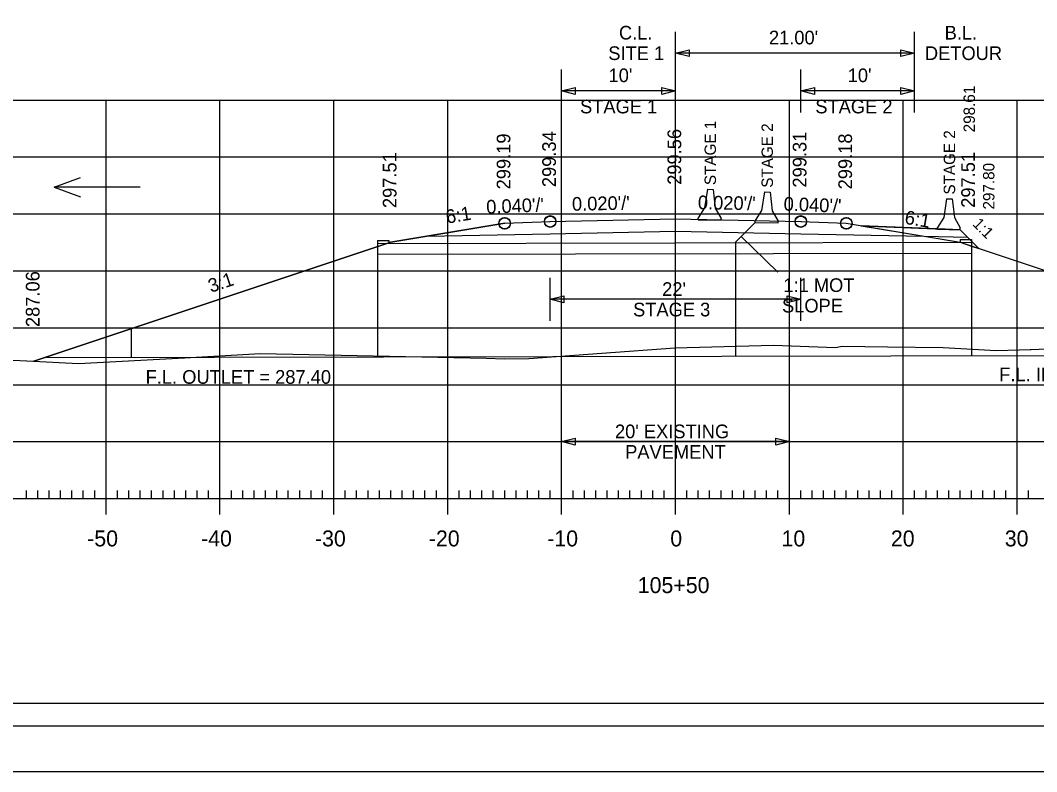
# Model space of a CAD drawing. Extents: x 1368713 to 1370673, y 380279 to 380950.
# Drawn here: x 1370094.8 to 1370184, y 380523.8 to 380589.8 of the extents above; entities that cross this region are included whole.
import ezdxf

# ---------------------------------------------------------------- set-up
doc = ezdxf.new("R2010")
doc.units = 0
for name, color, linetype in [('R_Alt Surface', 7, 'Continuous'), ('R_Axis', 7, 'Continuous'), ('R_Axis Annot', 7, 'Continuous'), ('R_Border', 7, 'Continuous'), ('R_CONC BARRIER', 7, 'Continuous'), ('R_Detour', 7, 'Continuous'), ('R_Exist Surface', 7, 'Continuous'), ('R_Fin Surface', 7, 'Continuous'), ('R_Grid', 7, 'Continuous'), ('R_No Plot', 7, 'Continuous'), ('R_ROW Annot', 7, 'Continuous'), ('R_Stage 3 EW', 7, 'Continuous'), ('R_Water', 7, 'Continuous'), ('R_Water Annot', 7, 'Continuous'), ('R_Xsect Elev', 7, 'Continuous'), ('R_Xsect Slope', 7, 'Continuous')]:
    doc.layers.add(name, color=color, linetype=linetype)

msp = doc.modelspace()

# ---------------------------------------------------------------- linework, layer by layer
for points in [[(1370141.283, 380572.113), (1370141.283, 380572.102), (1370141.283, 380572.091), (1370141.283, 380572.079), (1370141.283, 380572.068)], [(1370163.283, 380572.102), (1370163.283, 380572.091), (1370163.283, 380572.079), (1370163.283, 380572.068)]]:
    msp.add_lwpolyline(points)
at = {"layer": 'R_Alt Surface'}
for points in [[(1370137.283, 380571.931), (1370127.283, 380570.264)], [(1370167.283, 380571.931), (1370177.283, 380570.264)], [(1370130.442, 380570.791), (1370141.283, 380571.007), (1370152.283, 380571.227), (1370163.283, 380571.007), (1370174.123, 380570.791)], [(1370177.283, 380571.364), (1370178.139, 380570.508)], [(1370127.283, 380570.264), (1370095.937, 380559.815)], [(1370174.123, 380570.791), (1370177.932, 380570.714)], [(1370177.283, 380570.264), (1370207.014, 380560.354)]]:
    msp.add_lwpolyline(points, dxfattribs=at)
at = {"layer": 'R_Axis'}
for p, q in [((1370102.283, 380546.354), (1370102.283, 380549.154)), ((1370112.283, 380546.354), (1370112.283, 380549.154)), ((1370122.283, 380546.354), (1370122.283, 380549.154)), ((1370132.283, 380546.354), (1370132.283, 380549.154)), ((1370142.283, 380546.354), (1370142.283, 380549.154)), ((1370152.283, 380546.354), (1370152.283, 380549.154)), ((1370162.283, 380546.354), (1370162.283, 380549.154)), ((1370172.283, 380546.354), (1370172.283, 380549.154)), ((1370182.283, 380546.354), (1370182.283, 380549.154)), ((1370095.283, 380547.754), (1370095.283, 380548.454)), ((1370096.283, 380547.754), (1370096.283, 380548.454)), ((1370097.283, 380547.754), (1370097.283, 380548.454)), ((1370098.283, 380547.754), (1370098.283, 380548.454)), ((1370099.283, 380547.754), (1370099.283, 380548.454)), ((1370100.283, 380547.754), (1370100.283, 380548.454)), ((1370101.283, 380547.754), (1370101.283, 380548.454)), ((1370103.283, 380547.754), (1370103.283, 380548.454)), ((1370104.283, 380547.754), (1370104.283, 380548.454)), ((1370105.283, 380547.754), (1370105.283, 380548.454)), ((1370106.283, 380547.754), (1370106.283, 380548.454)), ((1370107.283, 380547.754), (1370107.283, 380548.454)), ((1370108.283, 380547.754), (1370108.283, 380548.454)), ((1370109.283, 380547.754), (1370109.283, 380548.454)), ((1370110.283, 380547.754), (1370110.283, 380548.454)), ((1370111.283, 380547.754), (1370111.283, 380548.454)), ((1370113.283, 380547.754), (1370113.283, 380548.454)), ((1370114.283, 380547.754), (1370114.283, 380548.454)), ((1370115.283, 380547.754), (1370115.283, 380548.454)), ((1370116.283, 380547.754), (1370116.283, 380548.454)), ((1370117.283, 380547.754), (1370117.283, 380548.454)), ((1370118.283, 380547.754), (1370118.283, 380548.454)), ((1370119.283, 380547.754), (1370119.283, 380548.454)), ((1370120.283, 380547.754), (1370120.283, 380548.454)), ((1370121.283, 380547.754), (1370121.283, 380548.454)), ((1370123.283, 380547.754), (1370123.283, 380548.454)), ((1370124.283, 380547.754), (1370124.283, 380548.454)), ((1370125.283, 380547.754), (1370125.283, 380548.454)), ((1370126.283, 380547.754), (1370126.283, 380548.454)), ((1370127.283, 380547.754), (1370127.283, 380548.454)), ((1370128.283, 380547.754), (1370128.283, 380548.454)), ((1370129.283, 380547.754), (1370129.283, 380548.454)), ((1370130.283, 380547.754), (1370130.283, 380548.454)), ((1370131.283, 380547.754), (1370131.283, 380548.454)), ((1370133.283, 380547.754), (1370133.283, 380548.454)), ((1370134.283, 380547.754), (1370134.283, 380548.454)), ((1370135.283, 380547.754), (1370135.283, 380548.454)), ((1370136.283, 380547.754), (1370136.283, 380548.454)), ((1370137.283, 380547.754), (1370137.283, 380548.454)), ((1370138.283, 380547.754), (1370138.283, 380548.454)), ((1370139.283, 380547.754), (1370139.283, 380548.454)), ((1370140.283, 380547.754), (1370140.283, 380548.454)), ((1370141.283, 380547.754), (1370141.283, 380548.454)), ((1370143.283, 380547.754), (1370143.283, 380548.454)), ((1370144.283, 380547.754), (1370144.283, 380548.454)), ((1370145.283, 380547.754), (1370145.283, 380548.454)), ((1370146.283, 380547.754), (1370146.283, 380548.454)), ((1370147.283, 380547.754), (1370147.283, 380548.454)), ((1370148.283, 380547.754), (1370148.283, 380548.454)), ((1370149.283, 380547.754), (1370149.283, 380548.454)), ((1370150.283, 380547.754), (1370150.283, 380548.454)), ((1370151.283, 380547.754), (1370151.283, 380548.454)), ((1370153.283, 380547.754), (1370153.283, 380548.454)), ((1370154.283, 380547.754), (1370154.283, 380548.454)), ((1370155.283, 380547.754), (1370155.283, 380548.454)), ((1370156.283, 380547.754), (1370156.283, 380548.454)), ((1370157.283, 380547.754), (1370157.283, 380548.454)), ((1370158.283, 380547.754), (1370158.283, 380548.454)), ((1370159.283, 380547.754), (1370159.283, 380548.454)), ((1370160.283, 380547.754), (1370160.283, 380548.454)), ((1370161.283, 380547.754), (1370161.283, 380548.454)), ((1370163.283, 380547.754), (1370163.283, 380548.454)), ((1370164.283, 380547.754), (1370164.283, 380548.454)), ((1370165.283, 380547.754), (1370165.283, 380548.454)), ((1370166.283, 380547.754), (1370166.283, 380548.454)), ((1370167.283, 380547.754), (1370167.283, 380548.454)), ((1370168.283, 380547.754), (1370168.283, 380548.454)), ((1370169.283, 380547.754), (1370169.283, 380548.454)), ((1370170.283, 380547.754), (1370170.283, 380548.454)), ((1370171.283, 380547.754), (1370171.283, 380548.454)), ((1370173.283, 380547.754), (1370173.283, 380548.454)), ((1370174.283, 380547.754), (1370174.283, 380548.454)), ((1370175.283, 380547.754), (1370175.283, 380548.454)), ((1370176.283, 380547.754), (1370176.283, 380548.454)), ((1370177.283, 380547.754), (1370177.283, 380548.454)), ((1370178.283, 380547.754), (1370178.283, 380548.454)), ((1370179.283, 380547.754), (1370179.283, 380548.454)), ((1370180.283, 380547.754), (1370180.283, 380548.454)), ((1370181.283, 380547.754), (1370181.283, 380548.454)), ((1370183.283, 380547.754), (1370183.283, 380548.454)), ((1370012.283, 380547.754), (1370292.283, 380547.754))]:
    msp.add_line(p, q, dxfattribs=at)
at = {"layer": 'R_Border'}
msp.add_line((1370310.463, 380527.754), (1369994.283, 380527.754), dxfattribs=at)
at = {"layer": 'R_CONC BARRIER'}
for p, q in [((1370155.086, 380574.917), (1370155.586, 380574.907)), ((1370160.089, 380574.688), (1370160.589, 380574.678)), ((1370176.087, 380574.088), (1370176.587, 380574.078)), ((1370154.283, 380572.233), (1370154.286, 380572.399)), ((1370154.283, 380572.233), (1370156.282, 380572.193)), ((1370156.282, 380572.193), (1370156.286, 380572.359)), ((1370159.285, 380572.004), (1370159.288, 380572.171)), ((1370159.285, 380572.004), (1370161.284, 380571.964)), ((1370161.284, 380571.964), (1370161.288, 380572.131)), ((1370175.283, 380571.404), (1370175.286, 380571.571)), ((1370175.283, 380571.404), (1370177.283, 380571.364)), ((1370177.283, 380571.364), (1370177.286, 380571.531))]:
    msp.add_line(p, q, dxfattribs=at)
for points in [[(1370155.086, 380574.917), (1370154.835, 380573.279), (1370154.286, 380572.399)], [(1370155.586, 380574.907), (1370155.772, 380573.26), (1370156.286, 380572.359)], [(1370160.089, 380574.688), (1370159.837, 380573.05), (1370159.288, 380572.171)], [(1370160.589, 380574.678), (1370160.774, 380573.032), (1370161.288, 380572.131)], [(1370176.087, 380574.088), (1370175.835, 380572.45), (1370175.286, 380571.571)], [(1370176.587, 380574.078), (1370176.773, 380572.432), (1370177.286, 380571.531)]]:
    msp.add_lwpolyline(points, dxfattribs=at)
at = {"layer": 'R_Detour'}
for p, q in [((1370159.285, 380572.004), (1370157.545, 380570.264)), ((1370157.545, 380570.264), (1370157.545, 380560.264)), ((1370161.274, 380567.633), (1370158.057, 380570.776))]:
    msp.add_line(p, q, dxfattribs=at)
at = {"layer": 'R_Exist Surface'}
msp.add_lwpolyline([(1370092.874, 380559.963), (1370095.324, 380559.844), (1370099.854, 380559.631), (1370109.161, 380560.101), (1370115.838, 380560.503), (1370135.654, 380560.071), (1370137.277, 380560.019), (1370139.399, 380560.046), (1370152.219, 380560.988), (1370160.894, 380561.239), (1370166.34, 380561.02), (1370166.917, 380561.13), (1370170.893, 380561.071), (1370175.781, 380561.031), (1370180.44, 380560.773), (1370182.469, 380560.82), (1370183.433, 380560.838), (1370183.506, 380560.845), (1370201.143, 380561.59)], dxfattribs=at)
at = {"layer": 'R_Fin Surface'}
for points in [[(1370095.937, 380559.815), (1370127.283, 380570.264), (1370130.442, 380570.791), (1370137.283, 380571.931), (1370141.283, 380572.091), (1370152.283, 380572.311), (1370163.283, 380572.091), (1370167.283, 380571.931), (1370174.123, 380570.791), (1370177.283, 380570.264), (1370207.014, 380560.354), (1370220.94, 380564.996)], [(1370137.283, 380571.931), (1370141.283, 380572.091), (1370152.283, 380572.311), (1370163.283, 380572.091), (1370167.283, 380571.931)], [(1370168.599, 380571.711), (1370177.283, 380571.364)]]:
    msp.add_lwpolyline(points, dxfattribs=at)
at = {"layer": 'R_Grid'}
for p, q in [((1370012.283, 380582.754), (1370292.283, 380582.754)), ((1370102.283, 380547.754), (1370102.283, 380582.754)), ((1370112.283, 380547.754), (1370112.283, 380582.754)), ((1370122.283, 380547.754), (1370122.283, 380582.754)), ((1370132.283, 380547.754), (1370132.283, 380582.754)), ((1370142.283, 380547.754), (1370142.283, 380582.754)), ((1370152.283, 380547.754), (1370152.283, 380582.754)), ((1370162.283, 380547.754), (1370162.283, 380582.754)), ((1370172.283, 380547.754), (1370172.283, 380582.754)), ((1370182.283, 380547.754), (1370182.283, 380582.754)), ((1370012.283, 380577.754), (1370292.283, 380577.754)), ((1370012.283, 380572.754), (1370292.283, 380572.754)), ((1370012.283, 380567.754), (1370292.283, 380567.754)), ((1370012.283, 380562.754), (1370292.283, 380562.754)), ((1370012.283, 380557.754), (1370292.283, 380557.754)), ((1370012.283, 380552.754), (1370292.283, 380552.754)), ((1370012.283, 380547.754), (1370292.283, 380547.754))]:
    msp.add_line(p, q, dxfattribs=at)
at = {"layer": 'R_No Plot'}
for points in [[(1369981.875, 380737.108), (1370315.215, 380737.108), (1370315.215, 380523.771), (1369981.875, 380523.771)], [(1369996.283, 380731.214), (1370245.823, 380731.214), (1370245.823, 380721.334), (1370263.363, 380721.334), (1370287.463, 380721.334), (1370287.463, 380699.001), (1370308.463, 380699.001), (1370308.463, 380529.754), (1369996.283, 380529.754)], [(1369996.283, 380628.484), (1370308.463, 380628.484), (1370308.463, 380529.754), (1369996.283, 380529.754)]]:
    msp.add_lwpolyline(points, close=True, dxfattribs=at)
for centre in [(1370137.283, 380571.942), (1370137.283, 380571.931), (1370137.283, 380571.931), (1370137.283, 380571.919), (1370137.283, 380571.908), (1370141.283, 380572.102), (1370141.283, 380572.091), (1370141.283, 380572.091), (1370141.283, 380572.079), (1370141.283, 380572.068), (1370163.283, 380572.102), (1370163.283, 380572.091), (1370163.283, 380572.091), (1370163.283, 380572.079), (1370163.283, 380572.068), (1370167.283, 380571.942), (1370167.283, 380571.931), (1370167.283, 380571.931), (1370167.283, 380571.919), (1370167.283, 380571.908)]:
    msp.add_circle(centre, 0.5, dxfattribs=at)
at = {"layer": 'R_ROW Annot'}
for p, q in [((1370152.283, 380584.988), (1370152.283, 380588.756)), ((1370173.283, 380584.988), (1370173.283, 380588.756)), ((1370173.283, 380586.872), (1370152.283, 380586.872)), ((1370142.283, 380581.67), (1370142.283, 380585.439)), ((1370152.283, 380581.67), (1370152.283, 380585.439)), ((1370163.283, 380581.67), (1370163.283, 380585.439)), ((1370173.283, 380581.67), (1370173.283, 380585.439)), ((1370152.283, 380583.555), (1370142.283, 380583.555)), ((1370173.283, 380583.555), (1370163.283, 380583.555)), ((1370141.283, 380563.369), (1370141.283, 380567.138)), ((1370163.283, 380563.369), (1370163.283, 380567.138)), ((1370163.283, 380565.254), (1370141.283, 380565.254)), ((1370142.283, 380550.869), (1370142.283, 380554.638)), ((1370162.283, 380550.869), (1370162.283, 380554.638)), ((1370162.283, 380552.754), (1370142.283, 380552.754))]:
    msp.add_line(p, q, dxfattribs=at)
for points in [[(1370153.483, 380586.572), (1370152.283, 380586.872), (1370153.483, 380587.172)], [(1370172.083, 380587.172), (1370173.283, 380586.872), (1370172.083, 380586.572)], [(1370143.483, 380583.255), (1370142.283, 380583.555), (1370143.483, 380583.855)], [(1370151.083, 380583.855), (1370152.283, 380583.555), (1370151.083, 380583.255)], [(1370164.483, 380583.255), (1370163.283, 380583.555), (1370164.483, 380583.855)], [(1370172.083, 380583.855), (1370173.283, 380583.555), (1370172.083, 380583.255)], [(1370142.483, 380564.954), (1370141.283, 380565.254), (1370142.483, 380565.554)], [(1370162.083, 380565.554), (1370163.283, 380565.254), (1370162.083, 380564.954)], [(1370143.483, 380552.454), (1370142.283, 380552.754), (1370143.483, 380553.054)], [(1370161.083, 380553.054), (1370162.283, 380552.754), (1370161.083, 380552.454)]]:
    msp.add_lwpolyline(points, close=True, dxfattribs=at)
at = {"layer": 'R_Stage 3 EW'}
for p, q in [((1370168.599, 380571.711), (1370174.123, 380570.791)), ((1370177.283, 380570.264), (1370178.283, 380569.931)), ((1370178.283, 380569.931), (1370178.933, 380569.714))]:
    msp.add_line(p, q, dxfattribs=at)
for points in [[(1370177.283, 380571.364), (1370175.284, 380571.444), (1370168.599, 380571.711)], [(1370178.097, 380570.55), (1370177.932, 380570.714), (1370177.283, 380571.364)], [(1370174.123, 380570.791), (1370177.071, 380570.299), (1370177.283, 380570.264)], [(1370178.933, 380569.714), (1370178.283, 380570.364), (1370178.097, 380570.55)]]:
    msp.add_lwpolyline(points, dxfattribs=at)
at = {"layer": 'R_Water'}
for p, q in [((1370126.114, 380570.165), (1370178.281, 380570.26)), ((1370126.116, 380570.417), (1370126.116, 380560.208)), ((1370126.116, 380570.417), (1370127.116, 380570.417)), ((1370127.116, 380570.417), (1370127.116, 380570.167)), ((1370177.283, 380570.508), (1370177.283, 380570.258)), ((1370177.283, 380570.508), (1370178.283, 380570.508)), ((1370178.283, 380570.508), (1370178.283, 380560.3)), ((1370126.116, 380569.207), (1370178.283, 380569.301)), ((1370104.493, 380562.667), (1370104.493, 380560.167)), ((1370096.951, 380560.154), (1370207.014, 380560.354))]:
    msp.add_line(p, q, dxfattribs=at)
at = {"layer": 'R_Water Annot'}
for p, q in [((1370097.732, 380575.098), (1370100.04, 380575.938)), ((1370105.273, 380575.098), (1370097.732, 380575.098)), ((1370097.732, 380575.098), (1370100.04, 380574.258))]:
    msp.add_line(p, q, dxfattribs=at)

# ---------------------------------------------------------------- texts
at = {"layer": 'R_Axis Annot'}
for s, p in [('-50', (1370100.624, 380543.554)), ('-40', (1370110.624, 380543.554)), ('-30', (1370120.624, 380543.554)), ('-20', (1370130.624, 380543.554)), ('-10', (1370141.02, 380543.554)), ('0', (1370151.825, 380543.554)), ('10', (1370161.594, 380543.554)), ('20', (1370171.197, 380543.554)), ('30', (1370181.197, 380543.554)), ('105+50', (1370148.97, 380539.454))]:
    msp.add_text(s, height=1.4, dxfattribs=at).set_placement(p)
at = {"layer": 'R_CONC BARRIER'}
for s, p in [(' STAGE 1', (1370155.836, 380574.912)), (' STAGE 2', (1370160.839, 380574.683)), (' STAGE 2', (1370176.837, 380574.083))]:
    msp.add_text(s, height=1, rotation=90, dxfattribs=at).set_placement(p)
at = {"layer": 'R_Detour'}
for s, p in [('1:1 MOT', (1370161.756, 380565.897)), ('SLOPE', (1370161.638, 380564.097))]:
    msp.add_text(s, height=1.2, dxfattribs=at).set_placement(p)
at = {"layer": 'R_ROW Annot'}
for s, p in [('C.L.', (1370147.319, 380588.068)), ('B.L.', (1370175.918, 380588.068)), ("21.00'", (1370160.487, 380587.642)), ('SITE 1', (1370146.383, 380586.269)), ('DETOUR', (1370174.185, 380586.269)), ("10'", (1370146.404, 380584.324)), ("10'", (1370167.404, 380584.324)), ('STAGE 1', (1370143.9, 380581.585)), ('STAGE 2', (1370164.56, 380581.585)), ("22'", (1370151.111, 380565.554)), ('STAGE 3', (1370148.56, 380563.754)), ("20' EXISTING", (1370146.968, 380553.054)), ('PAVEMENT', (1370147.865, 380551.254))]:
    msp.add_text(s, height=1.2, dxfattribs=at).set_placement(p)
at = {"layer": 'R_Xsect Elev'}
for s, height, p in [('298.61', 1, (1370178.578, 380579.919)), ('299.34', 1.2, (1370141.783, 380575.102)), ('299.56', 1.2, (1370152.783, 380575.311)), ('299.19', 1.2, (1370137.783, 380574.908)), ('299.31', 1.2, (1370163.783, 380575.068)), ('299.18', 1.2, (1370167.783, 380574.908)), ('297.51', 1.2, (1370127.783, 380573.264)), ('297.51', 1.2, (1370178.578, 380573.291)), ('297.80', 1, (1370180.289, 380573.141)), ('287.06', 1.2, (1370096.437, 380562.815))]:
    msp.add_text(s, height=height, rotation=90, dxfattribs=at).set_placement(p)
at = {"layer": 'R_Xsect Slope'}
for s, height, rotation, p in [("0.040'/'", 1.2, 2.29061, (1370135.687, 380572.768)), ("0.020'/'", 1.2, 1.14576, (1370143.203, 380573.029)), ("0.020'/'", 1.2, 358.85424, (1370154.239, 380573.172)), ("0.040'/'", 1.2, 357.70939, (1370161.759, 380573.052)), ('6:1', 1.2, 9.46234, (1370132.217, 380571.892)), ('6:1', 1.2, 350.53766, (1370172.348, 380571.892)), ('1:1', 1, 315, (1370178.308, 380571.803)), ('3:1', 1.2, 18.43493, (1370111.483, 380565.819)), ('F.L. OUTLET = 287.40', 1.2, 360, (1370105.756, 380557.836)), ('F.L. INLET = 287.60', 1.2, 360, (1370180.714, 380558.058))]:
    msp.add_text(s, height=height, rotation=rotation, dxfattribs=at).set_placement(p)

doc.saveas('drawing.dxf')
